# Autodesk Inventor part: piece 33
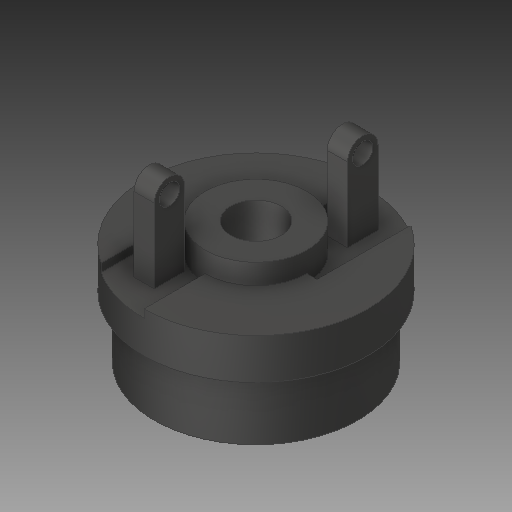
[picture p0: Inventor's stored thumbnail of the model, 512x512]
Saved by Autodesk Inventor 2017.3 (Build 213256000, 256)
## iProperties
Created: 2002-06
Part Number: piece 33
Material: Générique
Document SubType Name: Modeling
Designer: ficho
Density: 1 g/cm^3
Appearance: Par défaut
Author: ficho
Sending System: SolidWorks 2009
Last Author: christophe
Last Saved: 2011-02-10
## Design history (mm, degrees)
feature "Enlèv. mat.-Extru.12"
node "Solide1"
